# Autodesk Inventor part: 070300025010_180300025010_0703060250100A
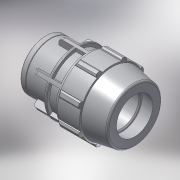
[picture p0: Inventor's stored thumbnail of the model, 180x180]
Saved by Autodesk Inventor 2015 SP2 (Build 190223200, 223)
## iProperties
Created: 2017-02
Part Number: 070300025010_180300025010_0703060250100A
Material: PVC-Piping
Description: PLASSON FEMALE ADAPTOR 25-1"
Document SubType Name: Modeling
Designer: KIM
Mass: 92.6774 g
Surface Area: 199.44 cm^2
Volume: 66.1981 cm^3
Density: 1.4 g/cm^3
Appearance: Smooth - White
Author: KIM
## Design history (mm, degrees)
derived "07030.ipt"
feature "Solid1::07030.ipt"
tag "TaggingFeature1"
body "Solid1"
other parameters: "d2" = 25, "d4" = 12.57143, "d5" = 22, "d7" = 54, "d9" = 12.57143, "d11" = 2.51429, "d12" = 43.2, "d13" = 120 deg, "d14" = 37.5, "d15" = 12 deg, "d16" = 48.6, "d18" = 1.25, "d19" = 35 deg, "d20" = 17.5 deg, "d21" = 50.22, "d23" = 0, "d25" = 360 deg, "d27" = 1.08, "d34" = 2.7, "d35" = 26.4, "d36" = 0, "d42" = 22, "d43" = 1.62, "d46" = 0.75, "d49" = 63, "d51" = 88, "d53" = 0.5, "d55" = 360 deg, "d61" = 21, "d63" = 30.291, "d64" = 29.33333, "d65" = 2.7, "d66" = 0.5, "d67" = 1, "d68" = 6.3, "d69" = 38.88, "d70" = 1.35, "d_" = 25, "E_" = 54, "H_" = 88, "l_" = 63, "l_2" = 21, "Rp_" = 30.291
